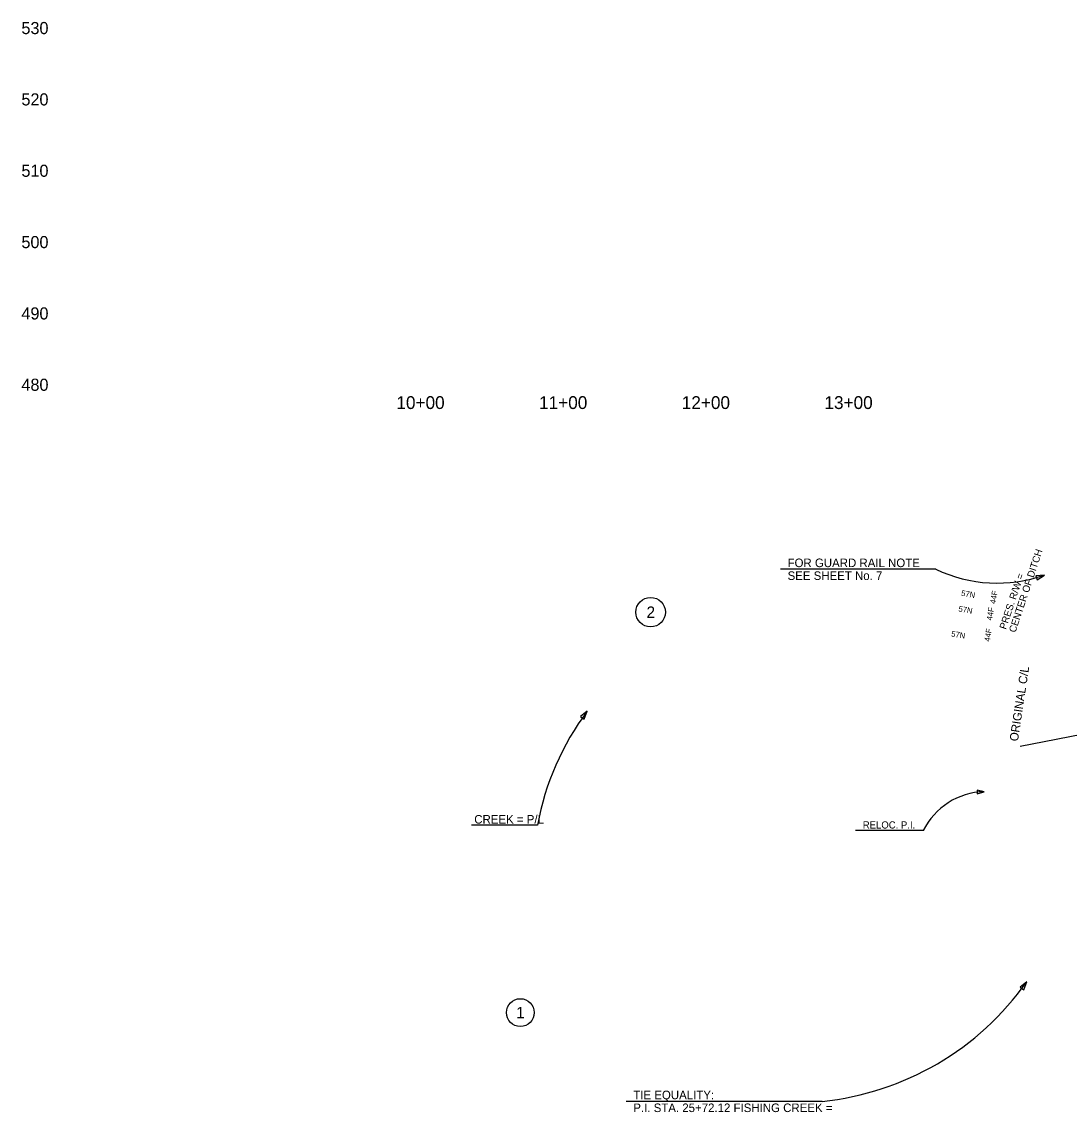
# Model space of a CAD drawing. Extents: x 1964849 to 1967422, y 1116563 to 1122211.
# Drawn here: x 1965766 to 1966500, y 1120670 to 1121434 of the extents above; entities that cross this region are included whole.
import ezdxf

# ---------------------------------------------------------------- set-up
doc = ezdxf.new("R2010")
doc.units = 0
for name, color, linetype in [('RD_DDB_Profile_Elev', 7, 'Continuous'), ('RD_DDB_StaTX', 7, 'Continuous'), ('RD_EX_DV_Prop', 7, 'Continuous'), ('RD_EX_DV_TX_Prop', 7, 'Continuous'), ('RD_EX_RW_TX', 7, 'Continuous'), ('RD_HC_Data', 7, 'Continuous'), ('RD_HC_Data_Rel', 7, 'Continuous'), ('RD_PD_TX_CstnLmt', 7, 'Continuous'), ('RD_TX_Drainage', 7, 'Continuous'), ('RD_TX_Misc1', 7, 'Continuous'), ('RD_TX_RoadID', 7, 'Continuous')]:
    doc.layers.add(name, color=color, linetype=linetype)

msp = doc.modelspace()

# ---------------------------------------------------------------- linework, layer by layer
at = {"layer": 'RD_EX_DV_Prop'}
msp.add_line((1966465.82, 1120926.48), (1966952.36, 1121022.03), dxfattribs=at)
at = {"layer": 'RD_EX_DV_TX_Prop'}
msp.add_line((1966127.58, 1120871.27), (1966081.28, 1120871.27), dxfattribs=at)
msp.add_lwpolyline([(1966160.28, 1120945.54), (1966162.51, 1120951.11), (1966157.79, 1120947.4)], close=True, dxfattribs=at)
for centre, radius in [((1966206.86, 1121020.43), 10.35), ((1966115.57, 1120739.82), 9.72)]:
    msp.add_circle(centre, radius, dxfattribs=at)
msp.add_arc((1966314.94, 1120836.87), 190.49, 143.14971, 169.5955, dxfattribs=at)
at = {"layer": 'RD_HC_Data'}
msp.add_line((1966327.04, 1120677.59), (1966189.74, 1120677.59), dxfattribs=at)
msp.add_lwpolyline([(1966468.39, 1120755.82), (1966470.47, 1120761.45), (1966465.85, 1120757.61)], close=True, dxfattribs=at)
msp.add_arc((1966306.42, 1120877.46), 200.93, 275.89189, 324.73454, dxfattribs=at)
at = {"layer": 'RD_HC_Data_Rel'}
msp.add_line((1966398, 1120867.33), (1966350.55, 1120867.33), dxfattribs=at)
msp.add_lwpolyline([(1966435.75, 1120893.21), (1966440.54, 1120894.64), (1966435.68, 1120895.79)], close=True, dxfattribs=at)
msp.add_arc((1966441.92, 1120845.69), 48.97, 91.61475, 153.7786, dxfattribs=at)
at = {"layer": 'RD_TX_Misc1'}
msp.add_line((1966406.78, 1121050.52), (1966297.85, 1121050.52), dxfattribs=at)
msp.add_lwpolyline([(1966477.87, 1121043.06), (1966482.82, 1121046.44), (1966476.84, 1121045.98)], close=True, dxfattribs=at)
msp.add_arc((1966449.73, 1121140.43), 99.63, 244.46334, 289.39296, dxfattribs=at)

# ---------------------------------------------------------------- texts
at = {"layer": 'RD_DDB_Profile_Elev'}
for s, p in [('530', (1965765.92, 1121425.58)), ('520', (1965765.92, 1121375.58)), ('510', (1965765.92, 1121325.58)), ('500', (1965765.92, 1121275.58)), ('490', (1965765.92, 1121225.58)), ('480', (1965765.92, 1121175.58))]:
    msp.add_text(s, height=8.5, dxfattribs=at).set_placement(p)
at = {"layer": 'RD_DDB_StaTX'}
for s, p in [('10+00', (1966028.71, 1121162.83)), ('11+00', (1966128.71, 1121162.83)), ('12+00', (1966228.71, 1121162.83)), ('13+00', (1966328.71, 1121162.83))]:
    msp.add_text(s, height=9, dxfattribs=at).set_placement(p)
at = {"layer": 'RD_EX_DV_TX_Prop'}
for s, height, p in [('2', 8, (1966204.02, 1121016.44)), ('CREEK = P/L', 6, (1966083.28, 1120872.27)), ('1', 8, (1966112.65, 1120735.83))]:
    msp.add_text(s, height=height, dxfattribs=at).set_placement(p)
at = {"layer": 'RD_EX_RW_TX'}
for s, p in [('CENTER OF DITCH', (1966462.52, 1121005.79)), ('PRES. R/W = ', (1966455.88, 1121007.99))]:
    msp.add_text(s, height=5, rotation=71.69078, dxfattribs=at).set_placement(p)
at = {"layer": 'RD_HC_Data'}
for s, p in [('TIE EQUALITY:', (1966194.74, 1120679.09)), ('P.I. STA. 25+72.12 FISHING CREEK =', (1966194.74, 1120670.09))]:
    msp.add_text(s, height=6, dxfattribs=at).set_placement(p)
at = {"layer": 'RD_HC_Data_Rel'}
msp.add_text('RELOC. P.I.', height=5, dxfattribs=at).set_placement((1966355.55, 1120868.83))
at = {"layer": 'RD_PD_TX_CstnLmt'}
for rotation, p in [(79.87294, (1966448.56, 1121026.05)), (80.15294, (1966446.13, 1121014.43)), (80.85294, (1966444.57, 1120999.6))]:
    msp.add_text('44F', height=4, rotation=rotation, dxfattribs=at).set_placement(p)
at = {"layer": 'RD_TX_Drainage'}
for rotation, p in [(349.87294, (1966424.26, 1121031.98)), (350.15294, (1966422.4, 1121020.96)), (350.70654, (1966417.33, 1121003.45))]:
    msp.add_text('57N', height=4, rotation=rotation, dxfattribs=at).set_placement(p)
at = {"layer": 'RD_TX_Misc1'}
for s, p in [('FOR GUARD RAIL NOTE', (1966302.85, 1121052.02)), ('SEE SHEET No. 7', (1966302.85, 1121043.02))]:
    msp.add_text(s, height=6, dxfattribs=at).set_placement(p)
at = {"layer": 'RD_TX_RoadID'}
msp.add_text('ORIGINAL C/L', height=6, rotation=81.38837, dxfattribs=at).set_placement((1966464.28, 1120929.64))

doc.saveas('drawing.dxf')
